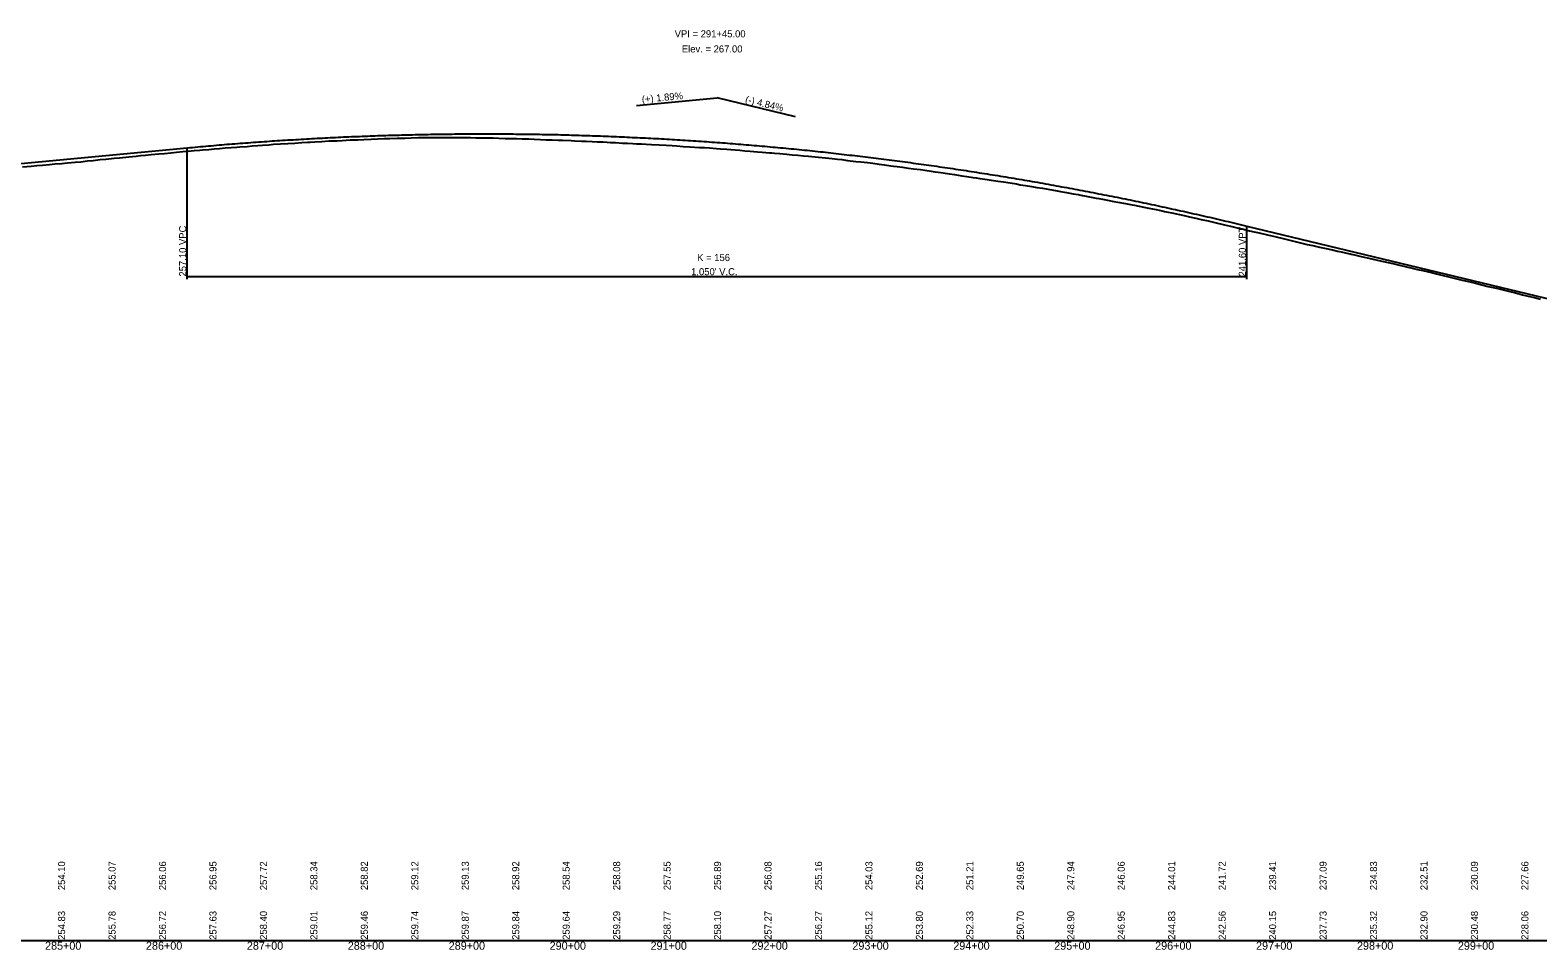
# Model space of a CAD drawing. Extents: x 1876258 to 1926563, y 729739 to 834437.
# Drawn here: x 1906827 to 1908321, y 827954 to 828865 of the extents above; entities that cross this region are included whole.
import ezdxf

# ---------------------------------------------------------------- set-up
doc = ezdxf.new("R2010")
doc.units = 0
for name, color, linetype in [('RD_EX_BldgApp', 7, 'Continuous'), ('RD_EX_H2O_BlueLn', 7, 'Continuous'), ('RD_EX_RailRoad', 7, 'Continuous'), ('RD_HC_Data', 7, 'Continuous'), ('RD_HC_TX_Sta50', 7, 'Continuous'), ('RD_PD_ALT3_CL', 7, 'Continuous'), ('RD_PD_ALT5_CL', 7, 'Continuous'), ('RD_PD_Final_Cl', 7, 'Continuous')]:
    doc.layers.add(name, color=color, linetype=linetype)

msp = doc.modelspace()

# ---------------------------------------------------------------- linework, layer by layer
at = {"layer": 'RD_EX_BldgApp'}
for points in [[(1906819.8, 828729.4), (1906828.6, 828730.2), (1906834.2, 828730.7), (1906839.8, 828731.2), (1906846.5, 828731.9), (1906851.9, 828732.3), (1906858.9, 828732.9), (1906864.5, 828733.4), (1906872.2, 828734.1), (1906877.6, 828734.6), (1906884.4, 828735.3), (1906889.9, 828735.8), (1906896.9, 828736.6), (1906902.6, 828737.1), (1906910.7, 828738), (1906916.1, 828738.4), (1906925.1, 828739.4), (1906932.4, 828740.2), (1906936.7, 828740.6), (1906941.8, 828741.1), (1906947.3, 828741.6), (1906955, 828742.3), (1906960.5, 828742.8), (1906966.9, 828743.5), (1906972.6, 828744.1), (1906978.6, 828744.6), (1906983.9, 828745), (1906990, 828745.6), (1906995.5, 828746), (1906998.2, 828746.3), (1907004.4, 828746.8), (1907009.9, 828747.3), (1907015.1, 828747.7), (1907020.6, 828748.2), (1907026.5, 828748.7), (1907032.2, 828749.1), (1907035.3, 828749.3), (1907042.5, 828749.8), (1907047.4, 828750.2), (1907052.9, 828750.6), (1907057.6, 828751), (1907063.9, 828751.4), (1907068.7, 828751.8), (1907075.6, 828752.2), (1907082.8, 828752.7), (1907089.7, 828753), (1907096.6, 828753.5), (1907102.2, 828753.9), (1907105, 828754), (1907109.6, 828754.3), (1907116.5, 828754.7), (1907123.3, 828755.1), (1907131.6, 828755.4), (1907136.5, 828755.7), (1907144.4, 828756.1), (1907152.1, 828756.4), (1907158, 828756.7), (1907165.4, 828757)], [(1907165.4, 828757), (1907171.9, 828757.2), (1907177.8, 828757.4), (1907183.8, 828757.7), (1907191.1, 828757.8), (1907198.8, 828758), (1907205, 828758.2), (1907212.4, 828758.4), (1907218.8, 828758.4), (1907224.6, 828758.5), (1907229.6, 828758.6), (1907237.3, 828758.6), (1907240.3, 828758.6), (1907246.1, 828758.5), (1907252.2, 828758.5), (1907258.2, 828758.5), (1907263.7, 828758.4), (1907269.1, 828758.3), (1907275.3, 828758.2), (1907278.7, 828758.2), (1907280.8, 828758.1), (1907286.2, 828758.1), (1907292, 828758), (1907298.3, 828757.7), (1907304, 828757.6), (1907309.3, 828757.5), (1907314.9, 828757.3), (1907318.9, 828757.1), (1907321.7, 828757.1), (1907326.8, 828756.8), (1907333, 828756.6), (1907338.9, 828756.4), (1907344.7, 828756.2), (1907350.8, 828756), (1907355.1, 828755.8), (1907363.5, 828755.5), (1907367, 828755.3), (1907373.9, 828755), (1907378.5, 828754.9), (1907384.3, 828754.6), (1907389.4, 828754.4), (1907395.4, 828754.1), (1907399.2, 828753.9), (1907402.4, 828753.7), (1907407.4, 828753.5), (1907414.5, 828753.1), (1907419.2, 828752.9), (1907424.5, 828752.6), (1907428.3, 828752.4), (1907433.3, 828752.2), (1907438, 828751.9), (1907443, 828751.6), (1907450.6, 828751.2), (1907457.6, 828750.9), (1907463.7, 828750.5), (1907468.3, 828750.2), (1907474.5, 828749.7), (1907481.1, 828749.3), (1907490.7, 828748.7), (1907495.7, 828748.5), (1907500.5, 828748.2), (1907507.4, 828747.7), (1907511.5, 828747.4), (1907517.7, 828746.9), (1907521.7, 828746.6), (1907530.8, 828745.9), (1907535.7, 828745.5), (1907540.9, 828745.1), (1907548.2, 828744.5), (1907552.9, 828744.1), (1907560, 828743.4), (1907562.5, 828743.2), (1907565, 828743), (1907570.2, 828742.6), (1907577.4, 828741.9), (1907582.6, 828741.5), (1907588, 828741), (1907593.9, 828740.5), (1907598.8, 828740), (1907605.2, 828739.4), (1907618.9, 828738), (1907622.2, 828737.7), (1907627.3, 828737.1), (1907631.7, 828736.7), (1907637.4, 828735.9), (1907645.7, 828734.9), (1907650.7, 828734.4), (1907657.1, 828733.7), (1907662.6, 828733), (1907668.9, 828732.2), (1907673.9, 828731.5), (1907680.4, 828730.6), (1907682.9, 828730.3), (1907686.7, 828729.8), (1907691.7, 828729.1), (1907697.9, 828728.3), (1907702.9, 828727.6), (1907709.7, 828726.7), (1907714, 828726.1), (1907720.4, 828725.2), (1907723.9, 828724.6)], [(1907723.9, 828724.6), (1907727.2, 828724.2), (1907732.1, 828723.5), (1907738.3, 828722.6), (1907743.3, 828721.8), (1907750.8, 828720.7), (1907755.7, 828720), (1907761.9, 828719), (1907765, 828718.5), (1907768.6, 828718), (1907773.6, 828717.2), (1907779.9, 828716.2), (1907786.3, 828715.3), (1907791.9, 828714.5), (1907798.5, 828713.5), (1907804.9, 828712.5), (1907808.6, 828711.8), (1907813.6, 828710.9), (1907819.9, 828710), (1907825, 828709.1), (1907830.6, 828708.2), (1907837.7, 828707), (1907843.6, 828706), (1907848.5, 828705.1), (1907854.4, 828704), (1907860.9, 828702.9), (1907865.9, 828702), (1907868.5, 828701.5), (1907873.7, 828700.5), (1907883.8, 828698.6), (1907886.5, 828698.1), (1907889.9, 828697.3), (1907895, 828696.4), (1907901.3, 828695.3), (1907907.1, 828694.2), (1907914.4, 828692.9), (1907919.5, 828691.9), (1907921.7, 828691.4), (1907931, 828689.5), (1907935.9, 828688.6), (1907943.2, 828687.2), (1907949, 828685.9), (1907951.4, 828685.3), (1907958.7, 828683.8), (1907971.1, 828681.2), (1907976.1, 828680.1), (1907982.6, 828678.7), (1907987.8, 828677.4), (1907994.6, 828675.9), (1908001.2, 828674.3), (1908010.9, 828671.9), (1908016.8, 828670.6), (1908023.5, 828669.1), (1908028.3, 828668), (1908035.8, 828666.2), (1908040.2, 828665.2), (1908045.3, 828664), (1908053.6, 828662.1), (1908060.8, 828660.4), (1908070.4, 828658), (1908078.4, 828656.2), (1908083.6, 828654.9), (1908093, 828652.6), (1908098.5, 828651.4), (1908105.1, 828650), (1908110, 828648.9), (1908118.1, 828647.1), (1908123, 828646), (1908126.4, 828645.3), (1908135.1, 828643.3), (1908135.3, 828643.2), (1908136.6, 828642.9), (1908139.9, 828642.2), (1908146.3, 828640.7), (1908151.1, 828639.6), (1908158.1, 828638), (1908163.7, 828636.8), (1908173, 828634.7), (1908177.8, 828633.6), (1908184.5, 828632.1), (1908189.9, 828630.9), (1908197, 828629.2), (1908202.3, 828627.9), (1908207.3, 828626.8), (1908216, 828624.7), (1908221, 828623.4), (1908227.5, 828621.9), (1908233.3, 828620.5), (1908241.1, 828618.5), (1908246.5, 828617.2), (1908254.2, 828615.4), (1908259.5, 828614.1), (1908265.8, 828612.6), (1908272.3, 828611), (1908280.3, 828609.2), (1908286.9, 828607.6), (1908292.4, 828606.3), (1908299.4, 828604.5), (1908306.1, 828602.8), (1908311.8, 828601.4), (1908318, 828600)], [(1908318, 828600), (1908324.1, 828598.5)]]:
    msp.add_lwpolyline(points, dxfattribs=at)
at = {"layer": 'RD_EX_H2O_BlueLn'}
for p, q in [((1906983.1, 828618.3), (1906983.1, 828748.3)), ((1908033.1, 828618.3), (1908033.1, 828670.8)), ((1906983.1, 828620.8), (1908033.1, 828620.8))]:
    msp.add_line(p, q, dxfattribs=at)
at = {"layer": 'RD_HC_TX_Sta50'}
for p in [(1907428.4, 828790.3), (1907585.8, 828779)]:
    msp.add_line(p, (1907508.1, 828797.8), dxfattribs=at)
at = {"layer": 'RD_PD_ALT5_CL'}
for p, q in [((1906248.1, 828679), (1906983.1, 828748.3)), ((1908033.1, 828670.8), (1908383.1, 828586.2))]:
    msp.add_line(p, q, dxfattribs=at)
msp.add_spline([(1906983.1, 828748.3), (1907004.1, 828750.2), (1907025.1, 828752), (1907046.1, 828753.6), (1907067.1, 828755.1), (1907088.1, 828756.4), (1907109.1, 828757.6), (1907130.1, 828758.7), (1907151.1, 828759.6), (1907172.1, 828760.4), (1907193.1, 828761), (1907214.1, 828761.5), (1907235.1, 828761.9), (1907256.1, 828762.1), (1907277.1, 828762.2), (1907298.1, 828762.1), (1907319.1, 828761.9), (1907340.1, 828761.6), (1907361.1, 828761.1), (1907382.1, 828760.4), (1907403.1, 828759.7), (1907424.1, 828758.7), (1907445.1, 828757.7), (1907466.1, 828756.5), (1907487.1, 828755.2), (1907508.1, 828753.7), (1907529.1, 828752.1), (1907550.1, 828750.3), (1907571.1, 828748.4), (1907592.1, 828746.4), (1907613.1, 828744.2), (1907634.1, 828741.8), (1907655.1, 828739.4), (1907676.1, 828736.8), (1907697.1, 828734), (1907718.1, 828731.1), (1907739.1, 828728.1), (1907760.1, 828724.9), (1907781.1, 828721.6), (1907802.1, 828718.2), (1907823.1, 828714.6), (1907844.1, 828710.8), (1907865.1, 828706.9), (1907886.1, 828702.9), (1907907.1, 828698.8), (1907928.1, 828694.5), (1907949.1, 828690), (1907970.1, 828685.4), (1907991.1, 828680.7), (1908012.1, 828675.8), (1908033.1, 828670.8)], degree=3, dxfattribs=at)
at = {"layer": 'RD_PD_Final_Cl'}
msp.add_line((1878363.1, 827962.8), (1926563.1, 827962.8), dxfattribs=at)

# ---------------------------------------------------------------- texts
at = {"layer": 'RD_EX_H2O_BlueLn'}
for s, p in [('K = 156', (1907488.4, 828636.1)), ("1,050' V.C.", (1907482.4, 828622.1))]:
    msp.add_text(s, height=7, dxfattribs=at).set_placement(p)
at = {"layer": 'RD_EX_RailRoad'}
for s, p in [('257.10 VPC', (1906982.1, 828620.8)), ('241.60 VPT', (1908032.1, 828620.8)), ('254.10', (1906862.1, 828012.8)), ('255.07', (1906912.1, 828012.8)), ('256.06', (1906962.1, 828012.8)), ('256.95', (1907012.1, 828012.8)), ('257.72', (1907062.1, 828012.8)), ('258.34', (1907112.1, 828012.8)), ('258.82', (1907162.1, 828012.8)), ('259.12', (1907212.1, 828012.8)), ('259.13', (1907262.1, 828012.8)), ('258.92', (1907312.1, 828012.8)), ('258.54', (1907362.1, 828012.8)), ('258.08', (1907412.1, 828012.8)), ('257.55', (1907462.1, 828012.8)), ('256.89', (1907512.1, 828012.8)), ('256.08', (1907562.1, 828012.8)), ('255.16', (1907612.1, 828012.8)), ('254.03', (1907662.1, 828012.8)), ('252.69', (1907712.1, 828012.8)), ('251.21', (1907762.1, 828012.8)), ('249.65', (1907812.1, 828012.8)), ('247.94', (1907862.1, 828012.8)), ('246.06', (1907912.1, 828012.8)), ('244.01', (1907962.1, 828012.8)), ('241.72', (1908012.1, 828012.8)), ('239.41', (1908062.1, 828012.8)), ('237.09', (1908112.1, 828012.8)), ('234.83', (1908162.1, 828012.8)), ('232.51', (1908212.1, 828012.8)), ('230.09', (1908262.1, 828012.8)), ('227.66', (1908312.1, 828012.8)), ('254.83', (1906862.1, 827963.6)), ('255.78', (1906912.1, 827963.6)), ('256.72', (1906962.1, 827963.6)), ('257.63', (1907012.1, 827963.6)), ('258.40', (1907062.1, 827963.6)), ('259.01', (1907112.1, 827963.6)), ('259.46', (1907162.1, 827963.6)), ('259.74', (1907212.1, 827963.6)), ('259.87', (1907262.1, 827963.6)), ('259.84', (1907312.1, 827963.6)), ('259.64', (1907362.1, 827963.6)), ('259.29', (1907412.1, 827963.6)), ('258.77', (1907462.1, 827963.6)), ('258.10', (1907512.1, 827963.6)), ('257.27', (1907562.1, 827963.6)), ('256.27', (1907612.1, 827963.6)), ('255.12', (1907662.1, 827963.6)), ('253.80', (1907712.1, 827963.6)), ('252.33', (1907762.1, 827963.6)), ('250.70', (1907812.1, 827963.6)), ('248.90', (1907862.1, 827963.6)), ('246.95', (1907912.1, 827963.6)), ('244.83', (1907962.1, 827963.6)), ('242.56', (1908012.1, 827963.6)), ('240.15', (1908062.1, 827963.6)), ('237.73', (1908112.1, 827963.6)), ('235.32', (1908162.1, 827963.6)), ('232.90', (1908212.1, 827963.6)), ('230.48', (1908262.1, 827963.6)), ('228.06', (1908312.1, 827963.6))]:
    msp.add_text(s, height=7, rotation=90, dxfattribs=at).set_placement(p)
at = {"layer": 'RD_HC_Data'}
for s, p in [('VPI = 291+45.00', (1907466.1, 828857.8)), ('Elev. = 267.00', (1907473.2, 828842.8))]:
    msp.add_text(s, height=7, dxfattribs=at).set_placement(p)
at = {"layer": 'RD_HC_TX_Sta50'}
for s, rotation, p in [('(+) 1.89%', 5.3877, (1907433.9, 828792.8)), ('(-) 4.84%', 346.403, (1907535.5, 828793.2))]:
    msp.add_text(s, height=7, rotation=rotation, dxfattribs=at).set_placement(p)
at = {"layer": 'RD_PD_ALT3_CL'}
for s, p in [('285+00', (1906842.2, 827953.8)), ('286+00', (1906942.2, 827953.8)), ('287+00', (1907042.2, 827953.8)), ('288+00', (1907142.2, 827953.8)), ('289+00', (1907242.2, 827953.8)), ('290+00', (1907342.2, 827953.8)), ('291+00', (1907442.2, 827953.8)), ('292+00', (1907542.2, 827953.8)), ('293+00', (1907642.2, 827953.8)), ('294+00', (1907742.2, 827953.8)), ('295+00', (1907842.2, 827953.8)), ('296+00', (1907942.2, 827953.8)), ('297+00', (1908042.2, 827953.8)), ('298+00', (1908142.2, 827953.8)), ('299+00', (1908242.2, 827953.8))]:
    msp.add_text(s, height=8, dxfattribs=at).set_placement(p)

doc.saveas('drawing.dxf')
